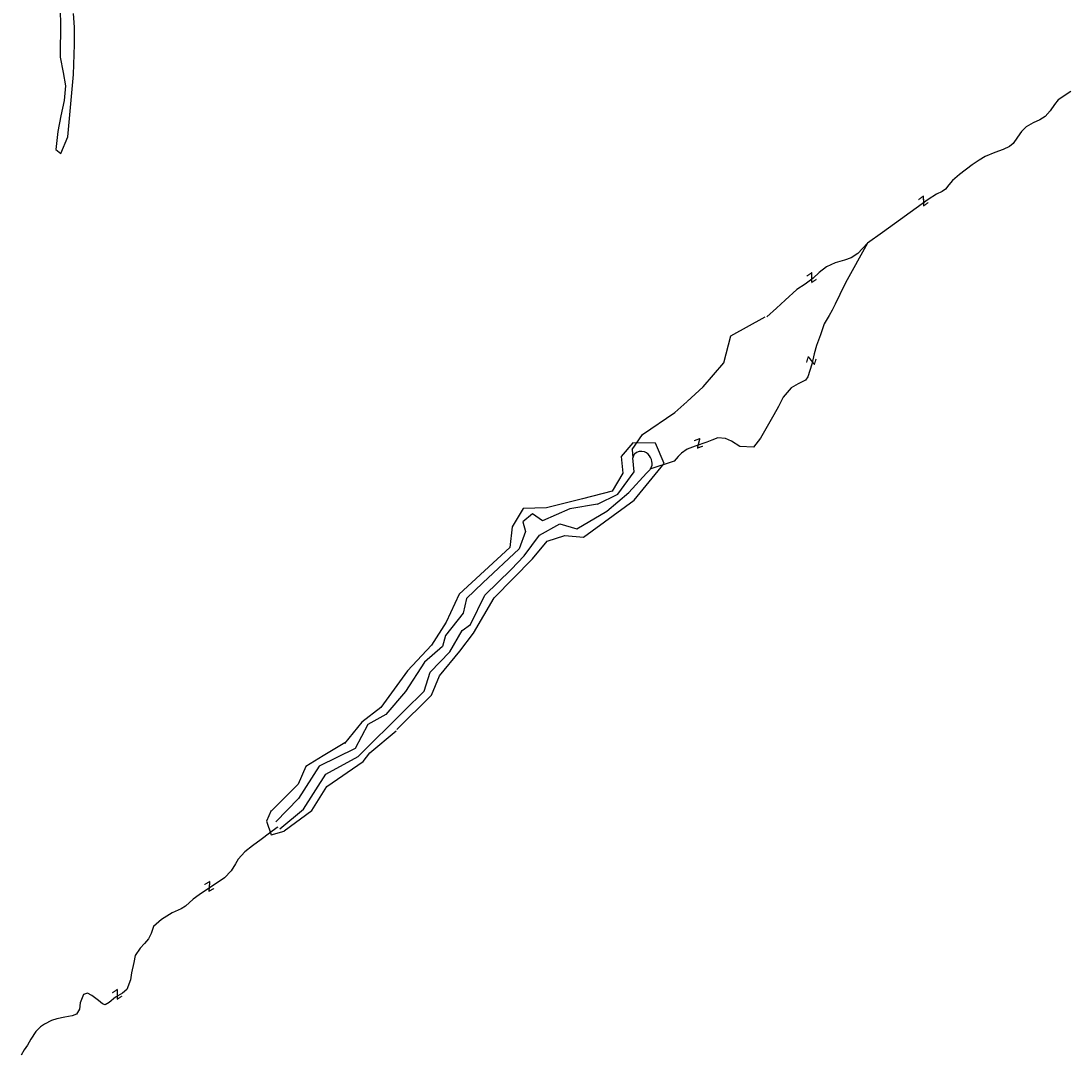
# Model space of a CAD drawing. Extents: x 2030130 to 2036320, y 723205 to 762423.
# Drawn here: x 2031485 to 2032356, y 752699 to 753557 of the extents above; entities that cross this region are included whole.
import ezdxf

# ---------------------------------------------------------------- set-up
doc = ezdxf.new("R2010")
doc.units = 0
for name, color, linetype in [('Draft_Station Tics Major', 7, 'Continuous'), ('Old_Level_51', 7, 'Continuous'), ('Prop Alignment Horizontal', 7, 'Continuous')]:
    doc.layers.add(name, color=color, linetype=linetype)

msp = doc.modelspace()

# ---------------------------------------------------------------- linework, layer by layer
at = {"layer": 'Draft_Station Tics Major'}
for points in [[(2031516.95, 753571.35), (2031517.35, 753555.9), (2031517.06, 753526.91), (2031519.63, 753513.98), (2031521.51, 753502.87), (2031520.52, 753490.86), (2031517.71, 753478.25), (2031515.19, 753465.07), (2031513.57, 753450.07), (2031517.64, 753446.77), (2031523.51, 753460.76), (2031528.1, 753512.46), (2031529.02, 753537.24), (2031528.92, 753551.73), (2031528.2, 753563.05)], [(2031796.35, 752968.92), (2031825.16, 752997.42), (2031831.7, 753013.44), (2031848.63, 753033.93), (2031860.09, 753048.98), (2031877.31, 753078.07), (2031909.09, 753110.43), (2031921.21, 753125.2), (2031935.76, 753129.95), (2031951.21, 753128.46), (2031993.22, 753159.28), (2032018.17, 753189.56), (2032011.04, 753206.48), (2031992.33, 753206.78), (2031982.53, 753195.5), (2031984.01, 753181.55), (2031975.1, 753166.7), (2031950.45, 753160.47), (2031920.63, 753152.79), (2031901.33, 753152.19), (2031892.12, 753137.05), (2031890.04, 753119.84), (2031848.16, 753081.25), (2031837.25, 753057.89), (2031825.07, 753038.89), (2031805.17, 753017.52), (2031783.04, 752987.34), (2031767.3, 752975.17), (2031753.04, 752957.36)], [(2031702.86, 752884.81), (2031726, 752901.8), (2031738.28, 752921.62), (2031768.5, 752942.39), (2031774.17, 752949.46), (2031795.89, 752967.87)], [(2031753.39, 752957.96), (2031735.45, 752947.11), (2031720.81, 752938.14), (2031714.67, 752923.51), (2031692, 752900.85)], [(2031692.3, 752901.63), (2031688.44, 752892.87), (2031692.3, 752881.59), (2031702.85, 752884.71)]]:
    msp.add_lwpolyline(points, dxfattribs=at)
at = {"layer": 'Old_Level_51'}
msp.add_lwpolyline([(2032037.2, 753241.18), (2032050.57, 753253.16), (2032067.65, 753273.09), (2032073.62, 753295.57), (2032101.94, 753311.35)], dxfattribs=at)
at = {"layer": 'Prop Alignment Horizontal'}
for p, q in [((2031991.72, 753201.36), (2031992.11, 753194.39)), ((2032026.51, 753191.69), (2032006.34, 753185.02)), ((2032003.68, 753181.59), (2031988.8, 753165.58)), ((2031962.98, 753155.86), (2031940.06, 753152))]:
    msp.add_line(p, q, dxfattribs=at)
for points in [[(2032355.68, 753498.44), (2032345.16, 753491.32), (2032341.96, 753487.45), (2032338.4, 753482.33), (2032334.35, 753477.5), (2032329.8, 753474.67), (2032324.28, 753472.39), (2032318.4, 753468.87), (2032314.63, 753465.1), (2032311.34, 753460.46), (2032307.68, 753455.16), (2032304.75, 753452.63), (2032299.34, 753450.07), (2032292.39, 753447.78), (2032284.5, 753444.33), (2032279.37, 753441.39), (2032273.69, 753437.49), (2032263.18, 753429.32), (2032257.51, 753424.56), (2032254.3, 753420.89), (2032251.58, 753417.31), (2032248.91, 753415.36), (2032244.06, 753413.01), (2032237.24, 753408.8), (2032199.35, 753381.43), (2032186.95, 753372.38), (2032178.93, 753363.95), (2032173.43, 753360.34), (2032167.82, 753358.35), (2032160.01, 753356.05), (2032152.88, 753352.8), (2032146.82, 753348.23), (2032141.82, 753343.38), (2032135.19, 753338.51), (2032128.17, 753334.02), (2032118.63, 753325.1), (2032111.26, 753318.59), (2032103.39, 753311.46)], [(2032186.95, 753372.38), (2032168.59, 753339.51), (2032163.95, 753329.91), (2032160.14, 753321.85), (2032157.54, 753316.76), (2032155.02, 753312.43), (2032151.01, 753305.61), (2032147.79, 753296.31), (2032144.57, 753287.59), (2032142.76, 753280.51), (2032140.58, 753271.99), (2032137.38, 753261.64), (2032135.32, 753258.85), (2032129.45, 753255.62), (2032123.48, 753252.3), (2032116.81, 753244.58), (2032112.92, 753237.03)], [(2031991.72, 753201.36), (2032000.22, 753213.65), (2032026.98, 753232.02), (2032036.91, 753240.92)], [(2032112.92, 753237.03), (2032112.91, 753236.99), (2032109.09, 753230.08), (2032105.73, 753224.31), (2032097.99, 753210.57), (2032092.27, 753203.34), (2032080.91, 753203.66), (2032074.08, 753208.15), (2032069.19, 753210.38), (2032062.7, 753210.86), (2032057.76, 753209.08), (2032053.49, 753207.4), (2032043.8, 753204.03), (2032037.35, 753201.46), (2032032.53, 753198.16), (2032029.9, 753195.36), (2032026.51, 753191.69)], [(2031962.98, 753155.86), (2031979.64, 753164.19), (2031993.31, 753182.8), (2031992.11, 753194.39)], [(2031850.77, 753051.01), (2031857.58, 753055.96), (2031869.31, 753080.54), (2031891.23, 753101.69), (2031902.01, 753113.02), (2031914.84, 753130.22), (2031931.64, 753139.59), (2031945.75, 753135.48), (2031970.68, 753150.16), (2031988.8, 753165.58)], [(2031940.02, 753152), (2031917.19, 753142.22), (2031908.84, 753147.88), (2031901.09, 753141.27), (2031903.15, 753133.28), (2031898.03, 753118.91), (2031867.71, 753090.78), (2031854.31, 753077.56), (2031851.51, 753065.59), (2031836.81, 753047.05)], [(2031836.81, 753047.05), (2031834.27, 753037.69), (2031819.32, 753024.92), (2031803.62, 753000.51), (2031787.27, 752981.29), (2031772.48, 752973.2), (2031761.84, 752953.12), (2031731.94, 752938.48), (2031714.9, 752911.57), (2031696.06, 752892.48)], [(2031699.29, 752886.67), (2031718.98, 752902.76), (2031737.54, 752931.83), (2031764.39, 752946.52), (2031802.82, 752984.71), (2031819.03, 753000.73), (2031824.12, 753016.61), (2031840.46, 753033.31), (2031850.77, 753051.01)], [(2031697.6, 752888.02), (2031697.24, 752887.76), (2031690.87, 752883.04), (2031683.93, 752877.73), (2031676.61, 752872.32), (2031670.34, 752867.51), (2031664.76, 752861.36), (2031662.71, 752857.58), (2031658.95, 752851.65), (2031653.37, 752845.98), (2031647.28, 752841.74), (2031639.47, 752836.52), (2031632.43, 752831.89), (2031627.48, 752828.25), (2031621.13, 752822.37), (2031617.41, 752820.2), (2031609.96, 752816.81), (2031601.2, 752811.18), (2031594.46, 752805.5), (2031592.53, 752799.79), (2031590.4, 752795.14), (2031587.09, 752791.43), (2031583.49, 752787.62), (2031579.46, 752781.4), (2031578.3, 752775.51), (2031576.22, 752766.92), (2031575.54, 752761.33), (2031572.59, 752753.29), (2031568.99, 752750.25), (2031563.17, 752746.89), (2031557.76, 752742.57), (2031554.61, 752740.6), (2031552.2, 752741.42), (2031548.88, 752744.16), (2031543.33, 752748.3), (2031539.74, 752750.07), (2031536.49, 752749.16), (2031533.62, 752742.18), (2031533.22, 752736.98)], [(2031533.22, 752736.98), (2031530.59, 752732.71), (2031527.25, 752731.4), (2031520.91, 752730.34), (2031514.3, 752728.98), (2031510.09, 752727.47), (2031504.27, 752724.59), (2031500.75, 752722.13), (2031496.96, 752718.51), (2031492.92, 752712), (2031490.02, 752707.05), (2031487.2, 752703.06), (2031484.67, 752698.88)]]:
    msp.add_lwpolyline(points, dxfattribs=at)
msp.add_spline([(2032003.68, 753181.59), (2032008.12, 753188.28), (2032006.93, 753194.52), (2032001.88, 753199.27), (2031993.57, 753197.48), (2031992.11, 753194.39)], degree=3, dxfattribs=at)

# ---------------------------------------------------------------- texts
for rotation, p in [(216.64492, (2032233.65, 753412.47)), (214.81936, (2032141.1, 753348.9)), (252.43944, (2032137.58, 753279.28)), (200.43971, (2032048.47, 753211.09)), (210.05908, (2031641.79, 752843.69)), (214.9911, (2031564.98, 752754.19))]:
    msp.add_text('z', height=10, rotation=rotation, dxfattribs=at).set_placement(p)

doc.saveas('drawing.dxf')
